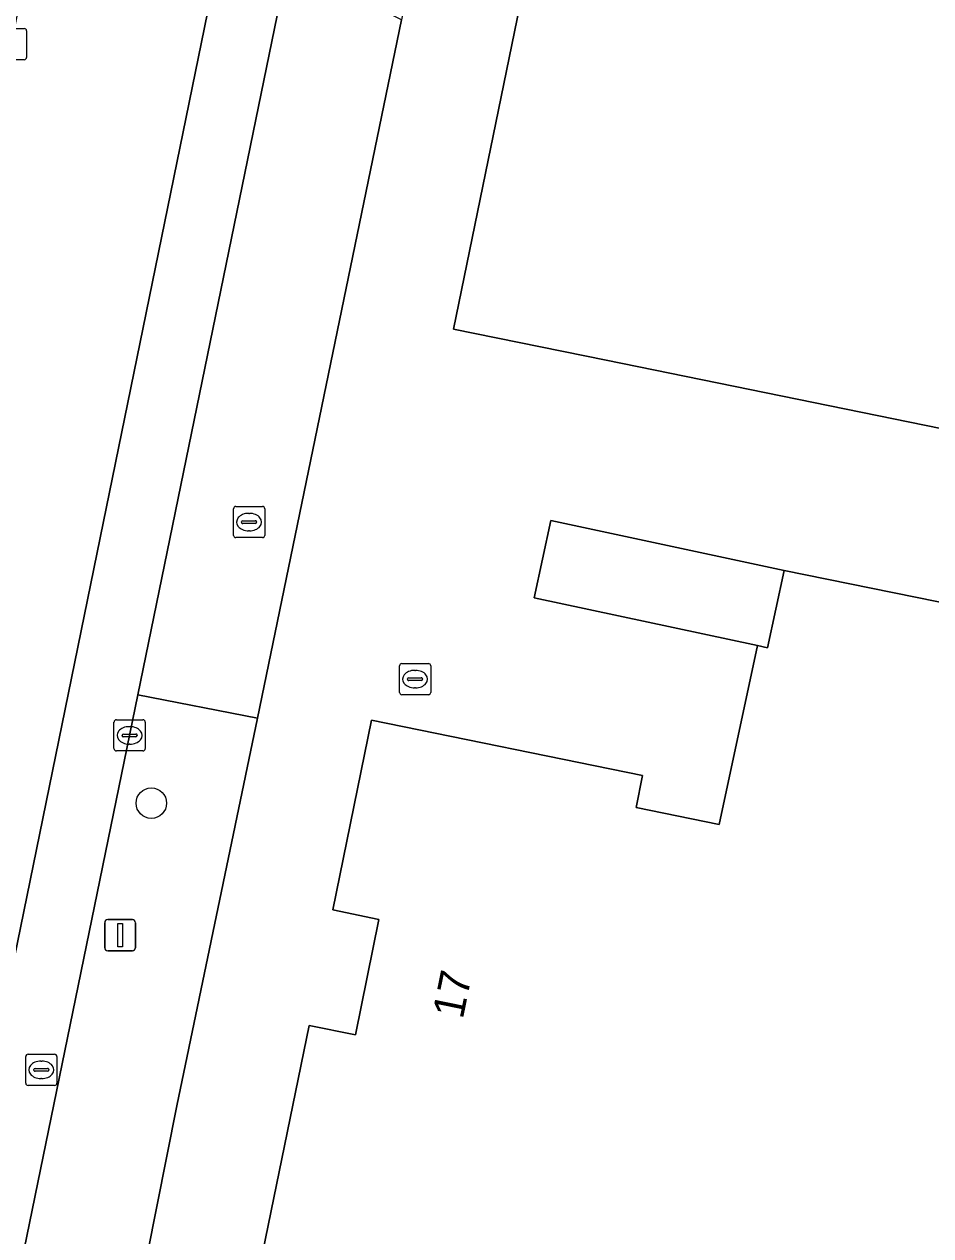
# Model space of a CAD drawing. Extents: x 157692 to 159674, y 381452 to 383291.
# Drawn here: x 158551.74 to 158580.82, y 382209.28 to 382248.15 of the extents above; entities that cross this region are included whole.
import ezdxf

# ---------------------------------------------------------------- set-up
doc = ezdxf.new("R2010")
doc.units = 0
for name, color, linetype in [('IMGEO_Boom', 7, 'Continuous'), ('IMGEO_Brandkraan', 7, 'Continuous'), ('IMGEO_Erf', 7, 'Continuous'), ('IMGEO_Kolk', 7, 'Continuous'), ('IMGEO_Lichtmast', 7, 'Continuous'), ('IMGEO_Pand', 7, 'Continuous'), ('IMGEO_Pand_nummerreeks', 7, 'Continuous'), ('IMGEO_Rijbaan_lokaal_gesloten', 7, 'Continuous'), ('IMGEO_Rijbaan_lokaal_open', 7, 'Continuous'), ('IMGEO_Rioolput', 7, 'Continuous'), ('IMGEO_Voetpad_open', 7, 'Continuous')]:
    doc.layers.add(name, color=color, linetype=linetype)

msp = doc.modelspace()

# ---------------------------------------------------------------- linework, layer by layer
at = {"layer": 'IMGEO_Boom'}
msp.add_circle((158555.821, 382223.161), 0.489, dxfattribs=at)
at = {"layer": 'IMGEO_Brandkraan'}
for p, q in [((158558.455, 382231.751), (158558.455, 382232.603)), ((158558.53, 382232.677), (158559.382, 382232.677)), ((158558.943, 382232.457), (158558.968, 382232.457)), ((158559.456, 382232.603), (158559.456, 382231.751)), ((158558.714, 382232.171), (158558.714, 382232.183)), ((158559.152, 382232.134), (158558.754, 382232.134)), ((158558.757, 382232.22), (158559.155, 382232.22)), ((158559.198, 382232.183), (158559.198, 382232.171)), ((158559.382, 382231.677), (158558.53, 382231.677)), ((158558.966, 382231.897), (158558.941, 382231.897))]:
    msp.add_line(p, q, dxfattribs=at)
for points in [[(158558.455, 382231.751), (158558.455, 382232.603)], [(158558.53, 382232.677), (158559.382, 382232.677)], [(158559.456, 382232.603), (158559.456, 382231.751)], [(158559.382, 382231.677), (158558.53, 382231.677)]]:
    msp.add_lwpolyline(points, dxfattribs=at)
for centre, radius, start, end in [((158558.532, 382232.601), 0.0765, 91.552, 178.448), ((158558.532, 382232.601), 0.0765, 91.552, 178.448), ((158559.38, 382232.601), 0.0765, 1.552, 88.448), ((158559.38, 382232.601), 0.0765, 1.552, 88.448), ((158558.754, 382232.18), 0.0403, 85.8775, 175.7526), ((158558.751, 382232.17), 0.0366, 178.938, 274.7102), ((158559.155, 382232.177), 0.043, 264.8664, 352.4533), ((158559.159, 382232.182), 0.0386, 1.7309, 96.639), ((158558.532, 382231.753), 0.0765, 181.552, 268.448), ((158558.532, 382231.753), 0.0765, 181.552, 268.448), ((158559.38, 382231.753), 0.0765, 271.552, 358.448), ((158559.38, 382231.753), 0.0765, 271.552, 358.448)]:
    msp.add_arc(centre, radius, start, end, dxfattribs=at)
for centre, major_axis, ratio, start_param, end_param in [((158558.942, 382232.177), (-0.387, 0.002), 0.722429, 4.712389, 7.853982), ((158558.967, 382232.177), (-0.39, 0.002), 0.717154, 1.570796, 4.712389)]:
    msp.add_ellipse(centre, major_axis=major_axis, ratio=ratio, start_param=start_param, end_param=end_param, dxfattribs=at)
at = {"layer": 'IMGEO_Erf'}
for points in [[(158774.915, 382281.626), (158583.923, 382320.599), (158578.836, 382321.712), (158578.49, 382320.049), (158577.977, 382317.433), (158573.17, 382294.226), (158571.648, 382286.878), (158568.676, 382272.426), (158569.594, 382272.252), (158568.934, 382269.03), (158568.022, 382269.232), (158563.842, 382248.283), (158559.221, 382225.883), (158556.642, 382213.448), (158553.461, 382197.47)], [(158581.669, 382235.069), (158570.413, 382237.369), (158565.514, 382238.37), (158567.892, 382250), (158570.108, 382260.839), (158567.371, 382261.4), (158568.934, 382269.03), (158570.422, 382268.718), (158571.142, 382272.247), (158569.655, 382272.552), (158572.367, 382285.794), (158578.962, 382284.444), (158579.611, 382287.573), (158581.414, 382287.202)], [(158558.961, 382206.635), (158560.882, 382216.032), (158562.364, 382215.729), (158563.119, 382219.432), (158561.639, 382219.733), (158562.884, 382225.827), (158571.578, 382224.05), (158571.367, 382223.019), (158574.032, 382222.478), (158575.263, 382228.214), (158568.104, 382229.749), (158568.635, 382232.223), (158576.115, 382230.619), (158581.016, 382229.628), (158629.34, 382219.832), (158624.324, 382195.285)]]:
    msp.add_lwpolyline(points, dxfattribs=at)
at = {"layer": 'IMGEO_Kolk'}
for p, q in [((158550.892, 382248.01), (158551.744, 382248.01)), ((158551.818, 382247.936), (158551.818, 382247.084)), ((158551.744, 382247.01), (158550.892, 382247.01)), ((158554.623, 382224.908), (158554.623, 382225.76)), ((158554.698, 382225.834), (158555.55, 382225.834)), ((158555.624, 382225.76), (158555.624, 382224.908)), ((158554.882, 382225.328), (158554.882, 382225.34)), ((158554.925, 382225.377), (158555.323, 382225.377)), ((158555.111, 382225.614), (158555.136, 382225.614)), ((158555.366, 382225.34), (158555.366, 382225.328)), ((158555.32, 382225.291), (158554.922, 382225.291)), ((158555.134, 382225.054), (158555.109, 382225.054)), ((158555.55, 382224.834), (158554.698, 382224.834))]:
    msp.add_line(p, q, dxfattribs=at)
for points in [[(158550.892, 382248.01), (158551.744, 382248.01)], [(158551.818, 382247.936), (158551.818, 382247.084)], [(158551.744, 382247.01), (158550.892, 382247.01)], [(158554.623, 382224.908), (158554.623, 382225.76)], [(158554.698, 382225.834), (158555.55, 382225.834)], [(158555.624, 382225.76), (158555.624, 382224.908)], [(158555.55, 382224.834), (158554.698, 382224.834)]]:
    msp.add_lwpolyline(points, dxfattribs=at)
for centre, radius, start, end in [((158551.742, 382247.934), 0.0765, 1.552, 88.448), ((158551.742, 382247.934), 0.0765, 1.552, 88.448), ((158551.742, 382247.086), 0.0765, 271.552, 358.448), ((158551.742, 382247.086), 0.0765, 271.552, 358.448), ((158554.7, 382225.758), 0.0765, 91.552, 178.448), ((158554.7, 382225.758), 0.0765, 91.552, 178.448), ((158555.548, 382225.758), 0.0765, 1.552, 88.448), ((158555.548, 382225.758), 0.0765, 1.552, 88.448), ((158554.922, 382225.337), 0.0403, 85.8775, 175.7526), ((158554.919, 382225.327), 0.0366, 178.938, 274.7102), ((158555.323, 382225.334), 0.043, 264.8664, 352.4533), ((158555.327, 382225.339), 0.0386, 1.7309, 96.639), ((158554.7, 382224.91), 0.0765, 181.552, 268.448), ((158554.7, 382224.91), 0.0765, 181.552, 268.448), ((158555.548, 382224.91), 0.0765, 271.552, 358.448), ((158555.548, 382224.91), 0.0765, 271.552, 358.448)]:
    msp.add_arc(centre, radius, start, end, dxfattribs=at)
for centre, major_axis, ratio, start_param, end_param in [((158555.11, 382225.334), (-0.387, 0.002), 0.722429, 4.712389, 7.853982), ((158555.135, 382225.334), (-0.39, 0.002), 0.717154, 1.570796, 4.712389)]:
    msp.add_ellipse(centre, major_axis=major_axis, ratio=ratio, start_param=start_param, end_param=end_param, dxfattribs=at)
at = {"layer": 'IMGEO_Lichtmast'}
for p, q in [((158554.324, 382218.524), (158554.324, 382219.324)), ((158554.324, 382219.324), (158554.324, 382218.524)), ((158554.424, 382219.424), (158555.214, 382219.424)), ((158555.214, 382219.424), (158554.424, 382219.424)), ((158555.314, 382219.324), (158555.314, 382218.524)), ((158555.314, 382218.524), (158555.314, 382219.324)), ((158555.214, 382218.424), (158554.424, 382218.424)), ((158554.424, 382218.424), (158555.214, 382218.424))]:
    msp.add_line(p, q, dxfattribs=at)
msp.add_lwpolyline([(158554.744, 382219.299), (158554.894, 382219.299), (158554.894, 382218.549), (158554.744, 382218.549), (158554.744, 382219.299)], dxfattribs=at)
for centre, start, end in [((158554.424, 382219.324), 90, 180), ((158554.424, 382219.324), 90, 180), ((158555.214, 382219.324), 0, 90), ((158555.214, 382219.324), 360, 90), ((158554.424, 382218.524), 180, 270), ((158554.424, 382218.524), 180, 270), ((158555.214, 382218.524), 270, 0), ((158555.214, 382218.524), 270, 0)]:
    msp.add_arc(centre, 0.1, start, end, dxfattribs=at)
at = {"layer": 'IMGEO_Pand'}
msp.add_lwpolyline([(158581.414, 382287.202), (158579.611, 382287.573), (158578.962, 382284.444), (158572.367, 382285.794), (158569.655, 382272.552), (158571.142, 382272.247), (158570.422, 382268.718), (158568.934, 382269.03), (158567.371, 382261.4), (158570.108, 382260.839), (158567.892, 382250), (158565.514, 382238.37), (158570.413, 382237.369), (158581.669, 382235.069)], dxfattribs=at)
for points in [[(158576.115, 382230.619), (158568.635, 382232.223), (158568.104, 382229.749), (158575.263, 382228.214), (158575.584, 382228.145)], [(158576.115, 382230.619), (158575.584, 382228.145), (158575.263, 382228.214), (158574.032, 382222.478), (158571.367, 382223.019), (158571.578, 382224.05), (158562.884, 382225.827), (158561.639, 382219.733), (158563.119, 382219.432), (158562.364, 382215.729), (158560.882, 382216.032), (158558.961, 382206.635), (158623.952, 382193.477), (158624.324, 382195.285), (158629.34, 382219.832), (158581.016, 382229.628)]]:
    msp.add_lwpolyline(points, close=True, dxfattribs=at)
at = {"layer": 'IMGEO_Rijbaan_lokaal_gesloten'}
for points in [[(158566.717, 382304.975), (158570.119, 382321.454), (158566.644, 382322.187), (158547.202, 382227.455), (158542.075, 382202.135), (158534.877, 382167.21), (158528.747, 382136.998), (158534.64, 382136.161), (158544.988, 382186.707), (158554.178, 382231.666)], [(158563.237, 382275.98), (158554.178, 382231.666), (158544.988, 382186.707), (158534.64, 382136.161), (158536.85, 382135.847), (158537.008, 382136.63), (158543.098, 382166.746), (158549.561, 382198.266), (158555.39, 382226.63), (158560.201, 382250.104)], [(158554.178, 382231.666), (158563.237, 382275.98)]]:
    msp.add_lwpolyline(points, dxfattribs=at)
at = {"layer": 'IMGEO_Rijbaan_lokaal_open'}
msp.add_lwpolyline([(158559.221, 382225.883), (158563.842, 382248.283), (158560.201, 382250.104), (158555.39, 382226.63)], close=True, dxfattribs=at)
at = {"layer": 'IMGEO_Rioolput'}
for p, q in [((158563.854, 382227.64), (158564.706, 382227.64)), ((158563.779, 382226.714), (158563.779, 382227.566)), ((158564.267, 382227.42), (158564.292, 382227.42)), ((158564.78, 382227.566), (158564.78, 382226.714)), ((158564.038, 382227.134), (158564.038, 382227.146)), ((158564.476, 382227.097), (158564.078, 382227.097)), ((158564.081, 382227.183), (158564.479, 382227.183)), ((158564.522, 382227.146), (158564.522, 382227.134)), ((158564.706, 382226.64), (158563.854, 382226.64)), ((158564.29, 382226.86), (158564.265, 382226.86)), ((158551.792, 382214.179), (158551.792, 382215.031)), ((158551.867, 382215.105), (158552.719, 382215.105)), ((158552.28, 382214.885), (158552.305, 382214.885)), ((158552.793, 382215.031), (158552.793, 382214.179)), ((158552.051, 382214.599), (158552.051, 382214.611)), ((158552.489, 382214.562), (158552.091, 382214.562)), ((158552.094, 382214.648), (158552.492, 382214.648)), ((158552.535, 382214.611), (158552.535, 382214.599)), ((158552.719, 382214.105), (158551.867, 382214.105)), ((158552.303, 382214.325), (158552.278, 382214.325))]:
    msp.add_line(p, q, dxfattribs=at)
for points in [[(158563.854, 382227.64), (158564.706, 382227.64)], [(158563.779, 382226.714), (158563.779, 382227.566)], [(158564.78, 382227.566), (158564.78, 382226.714)], [(158564.706, 382226.64), (158563.854, 382226.64)], [(158551.792, 382214.179), (158551.792, 382215.031)], [(158551.867, 382215.105), (158552.719, 382215.105)], [(158552.793, 382215.031), (158552.793, 382214.179)], [(158552.719, 382214.105), (158551.867, 382214.105)]]:
    msp.add_lwpolyline(points, dxfattribs=at)
for centre, radius, start, end in [((158563.856, 382227.564), 0.0765, 91.552, 178.448), ((158563.856, 382227.564), 0.0765, 91.552, 178.448), ((158564.704, 382227.564), 0.0765, 1.552, 88.448), ((158564.704, 382227.564), 0.0765, 1.552, 88.448), ((158564.078, 382227.143), 0.0403, 85.8775, 175.7526), ((158564.075, 382227.133), 0.0366, 178.938, 274.7102), ((158564.479, 382227.14), 0.043, 264.8664, 352.4533), ((158564.483, 382227.145), 0.0386, 1.7309, 96.639), ((158563.856, 382226.716), 0.0765, 181.552, 268.448), ((158563.856, 382226.716), 0.0765, 181.552, 268.448), ((158564.704, 382226.716), 0.0765, 271.552, 358.448), ((158564.704, 382226.716), 0.0765, 271.552, 358.448), ((158551.869, 382215.029), 0.0765, 91.552, 178.448), ((158551.869, 382215.029), 0.0765, 91.552, 178.448), ((158552.717, 382215.029), 0.0765, 1.552, 88.448), ((158552.717, 382215.029), 0.0765, 1.552, 88.448), ((158552.091, 382214.608), 0.0403, 85.8775, 175.7526), ((158552.088, 382214.598), 0.0366, 178.938, 274.7102), ((158552.492, 382214.605), 0.043, 264.8664, 352.4533), ((158552.496, 382214.61), 0.0386, 1.7309, 96.639), ((158551.869, 382214.181), 0.0765, 181.552, 268.448), ((158551.869, 382214.181), 0.0765, 181.552, 268.448), ((158552.717, 382214.181), 0.0765, 271.552, 358.448), ((158552.717, 382214.181), 0.0765, 271.552, 358.448)]:
    msp.add_arc(centre, radius, start, end, dxfattribs=at)
for centre, major_axis, ratio, start_param, end_param in [((158564.266, 382227.14), (-0.387, 0.002), 0.722429, 4.712389, 7.853982), ((158564.291, 382227.14), (-0.39, 0.002), 0.717154, 1.570796, 4.712389), ((158552.279, 382214.605), (-0.387, 0.002), 0.722429, 4.712389, 7.853982), ((158552.304, 382214.605), (-0.39, 0.002), 0.717154, 1.570796, 4.712389)]:
    msp.add_ellipse(centre, major_axis=major_axis, ratio=ratio, start_param=start_param, end_param=end_param, dxfattribs=at)
at = {"layer": 'IMGEO_Voetpad_open'}
msp.add_lwpolyline([(158549.561, 382198.266), (158553.461, 382197.47), (158556.642, 382213.448), (158559.221, 382225.883), (158555.39, 382226.63)], close=True, dxfattribs=at)

# ---------------------------------------------------------------- texts
at = {"layer": 'IMGEO_Pand_nummerreeks'}
msp.add_text('17', height=1, rotation=78.476, dxfattribs=at).set_placement((158565.809, 382216.205))

doc.saveas('drawing.dxf')
